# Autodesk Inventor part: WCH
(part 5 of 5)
hole "Díra1793" diameter "d16136" = 9.84314; stored, may be unused: countersink angle "d16140" = 90 deg, drill point angle "d16142" = 0 deg; dims "d16134" = 197, "d16135" = 318, "d16137" = 6, "d16138" = 4, "d16139" = 2, "d16141" = 8
hole "Díra1794" diameter "d16145" = 9.84314; stored, may be unused: countersink angle "d16149" = 90 deg, drill point angle "d16151" = 0 deg; dims "d16143" = 208, "d16144" = 318, "d16146" = 6, "d16147" = 4, "d16148" = 2, "d16150" = 8
hole "Díra1795" diameter "d16154" = 9.84314; stored, may be unused: countersink angle "d16158" = 90 deg, drill point angle "d16160" = 0 deg; dims "d16152" = 219, "d16153" = 318, "d16155" = 6, "d16156" = 4, "d16157" = 2, "d16159" = 8
hole "Díra1796" diameter "d16163" = 9.84314; stored, may be unused: countersink angle "d16167" = 90 deg, drill point angle "d16169" = 0 deg; dims "d16161" = 230, "d16162" = 318, "d16164" = 6, "d16165" = 4, "d16166" = 2, "d16168" = 8
hole "Díra1797" diameter "d16172" = 9.84314; stored, may be unused: countersink angle "d16176" = 90 deg, drill point angle "d16178" = 0 deg; dims "d16170" = 241, "d16171" = 318, "d16173" = 6, "d16174" = 4, "d16175" = 2, "d16177" = 8
hole "Díra1798" diameter "d16181" = 9.92157; stored, may be unused: countersink angle "d16185" = 90 deg, drill point angle "d16187" = 0 deg; dims "d16179" = 252, "d16180" = 318, "d16182" = 6, "d16183" = 4, "d16184" = 2, "d16186" = 8
hole "Díra1799" diameter "d16190" = 9.80392; stored, may be unused: countersink angle "d16194" = 90 deg, drill point angle "d16196" = 0 deg; dims "d16188" = 263, "d16189" = 318, "d16191" = 6, "d16192" = 4, "d16193" = 2, "d16195" = 8
hole "Díra1800" diameter "d16199" = 9.17647; stored, may be unused: countersink angle "d16203" = 90 deg, drill point angle "d16205" = 0 deg; dims "d16197" = 274, "d16198" = 318, "d16200" = 6, "d16201" = 4, "d16202" = 2, "d16204" = 8
hole "Díra1801" diameter "d16208" = 10; stored, may be unused: countersink angle "d16212" = 90 deg, drill point angle "d16214" = 0 deg; dims "d16206" = 285, "d16207" = 318, "d16209" = 6, "d16210" = 4, "d16211" = 2, "d16213" = 8
hole "Díra1802" diameter "d16217" = 10; stored, may be unused: countersink angle "d16221" = 90 deg, drill point angle "d16223" = 0 deg; dims "d16215" = 296, "d16216" = 318, "d16218" = 6, "d16219" = 4, "d16220" = 2, "d16222" = 8
hole "Díra1803" diameter "d16226" = 10; stored, may be unused: countersink angle "d16230" = 90 deg, drill point angle "d16232" = 0 deg; dims "d16224" = 307, "d16225" = 318, "d16227" = 6, "d16228" = 4, "d16229" = 2, "d16231" = 8
hole "Díra1804" diameter "d16235" = 10; stored, may be unused: countersink angle "d16239" = 90 deg, drill point angle "d16241" = 0 deg; dims "d16233" = 318, "d16234" = 318, "d16236" = 6, "d16237" = 4, "d16238" = 2, "d16240" = 8
hole "Díra1805" diameter "d16244" = 10; stored, may be unused: countersink angle "d16248" = 90 deg, drill point angle "d16250" = 0 deg; dims "d16242" = 329, "d16243" = 318, "d16245" = 6, "d16246" = 4, "d16247" = 2, "d16249" = 8
hole "Díra1806" diameter "d16253" = 10; stored, may be unused: countersink angle "d16257" = 90 deg, drill point angle "d16259" = 0 deg; dims "d16251" = 340, "d16252" = 318, "d16254" = 6, "d16255" = 4, "d16256" = 2, "d16258" = 8
hole "Díra1807" diameter "d16262" = 3.84314; stored, may be unused: countersink angle "d16266" = 90 deg, drill point angle "d16268" = 0 deg; dims "d16260" = 351, "d16261" = 318, "d16263" = 6, "d16264" = 4, "d16265" = 2, "d16267" = 8
hole "Díra1808" diameter "d16271" = 3.4902; stored, may be unused: countersink angle "d16275" = 90 deg, drill point angle "d16277" = 0 deg; dims "d16269" = 10, "d16270" = 329, "d16272" = 6, "d16273" = 4, "d16274" = 2, "d16276" = 8
hole "Díra1809" diameter "d16280" = 3.33333; stored, may be unused: countersink angle "d16284" = 90 deg, drill point angle "d16286" = 0 deg; dims "d16278" = 21, "d16279" = 329, "d16281" = 6, "d16282" = 4, "d16283" = 2, "d16285" = 8
hole "Díra1810" diameter "d16289" = 3.83007; stored, may be unused: countersink angle "d16293" = 90 deg, drill point angle "d16295" = 0 deg; dims "d16287" = 32, "d16288" = 329, "d16290" = 6, "d16291" = 4, "d16292" = 2, "d16294" = 8
hole "Díra1811" diameter "d16298" = 3.4902; stored, may be unused: countersink angle "d16302" = 90 deg, drill point angle "d16304" = 0 deg; dims "d16296" = 43, "d16297" = 329, "d16299" = 6, "d16300" = 4, "d16301" = 2, "d16303" = 8
hole "Díra1812" diameter "d16307" = 2.66667; stored, may be unused: countersink angle "d16311" = 90 deg, drill point angle "d16313" = 0 deg; dims "d16305" = 54, "d16306" = 329, "d16308" = 6, "d16309" = 4, "d16310" = 2, "d16312" = 8
hole "Díra1813" diameter "d16316" = 2.66667; stored, may be unused: countersink angle "d16320" = 90 deg, drill point angle "d16322" = 0 deg; dims "d16314" = 65, "d16315" = 329, "d16317" = 6, "d16318" = 4, "d16319" = 2, "d16321" = 8
hole "Díra1814" diameter "d16325" = 2.7451; stored, may be unused: countersink angle "d16329" = 90 deg, drill point angle "d16331" = 0 deg; dims "d16323" = 76, "d16324" = 329, "d16326" = 6, "d16327" = 4, "d16328" = 2, "d16330" = 8
hole "Díra1815" diameter "d16334" = 8.90196; stored, may be unused: countersink angle "d16338" = 90 deg, drill point angle "d16340" = 0 deg; dims "d16332" = 87, "d16333" = 329, "d16335" = 6, "d16336" = 4, "d16337" = 2, "d16339" = 8
hole "Díra1816" diameter "d16343" = 10; stored, may be unused: countersink angle "d16347" = 90 deg, drill point angle "d16349" = 0 deg; dims "d16341" = 98, "d16342" = 329, "d16344" = 6, "d16345" = 4, "d16346" = 2, "d16348" = 8
hole "Díra1817" diameter "d16352" = 10; stored, may be unused: countersink angle "d16356" = 90 deg, drill point angle "d16358" = 0 deg; dims "d16350" = 109, "d16351" = 329, "d16353" = 6, "d16354" = 4, "d16355" = 2, "d16357" = 8
hole "Díra1818" diameter "d16361" = 10; stored, may be unused: countersink angle "d16365" = 90 deg, drill point angle "d16367" = 0 deg; dims "d16359" = 120, "d16360" = 329, "d16362" = 6, "d16363" = 4, "d16364" = 2, "d16366" = 8
hole "Díra1819" diameter "d16370" = 10; stored, may be unused: countersink angle "d16374" = 90 deg, drill point angle "d16376" = 0 deg; dims "d16368" = 131, "d16369" = 329, "d16371" = 6, "d16372" = 4, "d16373" = 2, "d16375" = 8
hole "Díra1820" diameter "d16379" = 10; stored, may be unused: countersink angle "d16383" = 90 deg, drill point angle "d16385" = 0 deg; dims "d12975" = 109, "d12976" = 186, "d16377" = 142, "d16378" = 329, "d16380" = 6, "d16381" = 4, "d16382" = 2, "d16384" = 8
hole "Díra1821" diameter "d16388" = 9.68628; stored, may be unused: countersink angle "d16392" = 90 deg, drill point angle "d16394" = 0 deg; dims "d16386" = 153, "d16387" = 329, "d16389" = 6, "d16390" = 4, "d16391" = 2, "d16393" = 8
hole "Díra1822" diameter "d16397" = 9.45098; stored, may be unused: countersink angle "d16401" = 90 deg, drill point angle "d16403" = 0 deg; dims "d16395" = 164, "d16396" = 329, "d16398" = 6, "d16399" = 4, "d16400" = 2, "d16402" = 8
hole "Díra1823" diameter "d16406" = 9.41177; stored, may be unused: countersink angle "d16410" = 90 deg, drill point angle "d16412" = 0 deg; dims "d16404" = 175, "d16405" = 329, "d16407" = 6, "d16408" = 4, "d16409" = 2, "d16411" = 8
hole "Díra1824" diameter "d16415" = 8.98039; stored, may be unused: countersink angle "d16419" = 90 deg, drill point angle "d16421" = 0 deg; dims "d16413" = 186, "d16414" = 329, "d16416" = 6, "d16417" = 4, "d16418" = 2, "d16420" = 8
hole "Díra1825" diameter "d16424" = 8.90196; stored, may be unused: countersink angle "d16428" = 90 deg, drill point angle "d16430" = 0 deg; dims "d16422" = 197, "d16423" = 329, "d16425" = 6, "d16426" = 4, "d16427" = 2, "d16429" = 8
hole "Díra1826" diameter "d16433" = 8.78431; stored, may be unused: countersink angle "d16437" = 90 deg, drill point angle "d16439" = 0 deg; dims "d16431" = 208, "d16432" = 329, "d16434" = 6, "d16435" = 4, "d16436" = 2, "d16438" = 8
hole "Díra1827" diameter "d16442" = 8.43137; stored, may be unused: countersink angle "d16446" = 90 deg, drill point angle "d16448" = 0 deg; dims "d16440" = 219, "d16441" = 329, "d16443" = 6, "d16444" = 4, "d16445" = 2, "d16447" = 8
hole "Díra1828" diameter "d16451" = 8.39216; stored, may be unused: countersink angle "d16455" = 90 deg, drill point angle "d16457" = 0 deg; dims "d16449" = 230, "d16450" = 329, "d16452" = 6, "d16453" = 4, "d16454" = 2, "d16456" = 8
hole "Díra1829" diameter "d16460" = 7.96078; stored, may be unused: countersink angle "d16464" = 90 deg, drill point angle "d16466" = 0 deg; dims "d16458" = 241, "d16459" = 329, "d16461" = 6, "d16462" = 4, "d16463" = 2, "d16465" = 8
hole "Díra1830" diameter "d16469" = 7.80392; stored, may be unused: countersink angle "d16473" = 90 deg, drill point angle "d16475" = 0 deg; dims "d16467" = 252, "d16468" = 329, "d16470" = 6, "d16471" = 4, "d16472" = 2, "d16474" = 8
hole "Díra1831" diameter "d16478" = 7.29412; stored, may be unused: countersink angle "d16482" = 90 deg, drill point angle "d16484" = 0 deg; dims "d16476" = 263, "d16477" = 329, "d16479" = 6, "d16480" = 4, "d16481" = 2, "d16483" = 8
hole "Díra1832" diameter "d16487" = 7.68628; stored, may be unused: countersink angle "d16491" = 90 deg, drill point angle "d16493" = 0 deg; dims "d16485" = 274, "d16486" = 329, "d16488" = 6, "d16489" = 4, "d16490" = 2, "d16492" = 8
hole "Díra1833" diameter "d16496" = 4.62745; stored, may be unused: countersink angle "d16500" = 90 deg, drill point angle "d16502" = 0 deg; dims "d16494" = 285, "d16495" = 329, "d16497" = 6, "d16498" = 4, "d16499" = 2, "d16501" = 8
hole "Díra1834" diameter "d16505" = 2.66667; stored, may be unused: countersink angle "d16509" = 90 deg, drill point angle "d16511" = 0 deg; dims "d16503" = 296, "d16504" = 329, "d16506" = 6, "d16507" = 4, "d16508" = 2, "d16510" = 8
hole "Díra1835" diameter "d16514" = 4.82353; stored, may be unused: countersink angle "d16518" = 90 deg, drill point angle "d16520" = 0 deg; dims "d16512" = 307, "d16513" = 329, "d16515" = 6, "d16516" = 4, "d16517" = 2, "d16519" = 8
hole "Díra1836" diameter "d16523" = 5.64706; stored, may be unused: countersink angle "d16527" = 90 deg, drill point angle "d16529" = 0 deg; dims "d16521" = 318, "d16522" = 329, "d16524" = 6, "d16525" = 4, "d16526" = 2, "d16528" = 8
hole "Díra1837" diameter "d16532" = 4.78431; stored, may be unused: countersink angle "d16536" = 90 deg, drill point angle "d16538" = 0 deg; dims "d16530" = 329, "d16531" = 329, "d16533" = 6, "d16534" = 4, "d16535" = 2, "d16537" = 8
hole "Díra1838" diameter "d16541" = 2.56209; stored, may be unused: countersink angle "d16545" = 90 deg, drill point angle "d16547" = 0 deg; dims "d16539" = 340, "d16540" = 329, "d16542" = 6, "d16543" = 4, "d16544" = 2, "d16546" = 8
hole "Díra1839" diameter "d16550" = 0.78431; stored, may be unused: countersink angle "d16554" = 90 deg, drill point angle "d16556" = 0 deg; dims "d16548" = 351, "d16549" = 329, "d16551" = 6, "d16552" = 4, "d16553" = 2, "d16555" = 8
hole "Díra1840" diameter "d16559" = 4.19608; stored, may be unused: countersink angle "d16563" = 90 deg, drill point angle "d16565" = 0 deg; dims "d16557" = 10, "d16558" = 340, "d16560" = 6, "d16561" = 4, "d16562" = 2, "d16564" = 8
hole "Díra1841" diameter "d16568" = 4.90196; stored, may be unused: countersink angle "d16572" = 90 deg, drill point angle "d16574" = 0 deg; dims "d16566" = 21, "d16567" = 340, "d16569" = 6, "d16570" = 4, "d16571" = 2, "d16573" = 8
hole "Díra1842" diameter "d16577" = 5.41177; stored, may be unused: countersink angle "d16581" = 90 deg, drill point angle "d16583" = 0 deg; dims "d16575" = 32, "d16576" = 340, "d16578" = 6, "d16579" = 4, "d16580" = 2, "d16582" = 8
hole "Díra1843" diameter "d16586" = 3.84314; stored, may be unused: countersink angle "d16590" = 90 deg, drill point angle "d16592" = 0 deg; dims "d16584" = 43, "d16585" = 340, "d16587" = 6, "d16588" = 4, "d16589" = 2, "d16591" = 8
hole "Díra1844" diameter "d16595" = 2.19608; stored, may be unused: countersink angle "d16599" = 90 deg, drill point angle "d16601" = 0 deg; dims "d16593" = 54, "d16594" = 340, "d16596" = 6, "d16597" = 4, "d16598" = 2, "d16600" = 8
hole "Díra1845" diameter "d16604" = 1.52941; stored, may be unused: countersink angle "d16608" = 90 deg, drill point angle "d16610" = 0 deg; dims "d16602" = 65, "d16603" = 340, "d16605" = 6, "d16606" = 4, "d16607" = 2, "d16609" = 8
hole "Díra1846" diameter "d16613" = 1.29412; stored, may be unused: countersink angle "d16617" = 90 deg, drill point angle "d16619" = 0 deg; dims "d16611" = 76, "d16612" = 340, "d16614" = 6, "d16615" = 4, "d16616" = 2, "d16618" = 8
hole "Díra1847" diameter "d16622" = 8.54902; stored, may be unused: countersink angle "d16626" = 90 deg, drill point angle "d16628" = 0 deg; dims "d16620" = 87, "d16621" = 340, "d16623" = 6, "d16624" = 4, "d16625" = 2, "d16627" = 8
hole "Díra1848" diameter "d16631" = 10; stored, may be unused: countersink angle "d16635" = 90 deg, drill point angle "d16637" = 0 deg; dims "d16629" = 98, "d16630" = 340, "d16632" = 6, "d16633" = 4, "d16634" = 2, "d16636" = 8
hole "Díra1849" diameter "d16640" = 10; stored, may be unused: countersink angle "d16644" = 90 deg, drill point angle "d16646" = 0 deg; dims "d16638" = 109, "d16639" = 340, "d16641" = 6, "d16642" = 4, "d16643" = 2, "d16645" = 8
hole "Díra1850" diameter "d16649" = 10; stored, may be unused: countersink angle "d16653" = 90 deg, drill point angle "d16655" = 0 deg; dims "d16647" = 120, "d16648" = 340, "d16650" = 6, "d16651" = 4, "d16652" = 2, "d16654" = 8
hole "Díra1851" diameter "d16658" = 10; stored, may be unused: countersink angle "d16662" = 90 deg, drill point angle "d16664" = 0 deg; dims "d16656" = 131, "d16657" = 340, "d16659" = 6, "d16660" = 4, "d16661" = 2, "d16663" = 8
hole "Díra1852" diameter "d16667" = 10; stored, may be unused: countersink angle "d16671" = 90 deg, drill point angle "d16673" = 0 deg; dims "d16665" = 142, "d16666" = 340, "d16668" = 6, "d16669" = 4, "d16670" = 2, "d16672" = 8
hole "Díra1853" diameter "d16676" = 10; stored, may be unused: countersink angle "d16680" = 90 deg, drill point angle "d16682" = 0 deg; dims "d16674" = 153, "d16675" = 340, "d16677" = 6, "d16678" = 4, "d16679" = 2, "d16681" = 8
hole "Díra1854" diameter "d16685" = 10; stored, may be unused: countersink angle "d16689" = 90 deg, drill point angle "d16691" = 0 deg; dims "d16683" = 164, "d16684" = 340, "d16686" = 6, "d16687" = 4, "d16688" = 2, "d16690" = 8
hole "Díra1855" diameter "d16694" = 10; stored, may be unused: countersink angle "d16698" = 90 deg, drill point angle "d16700" = 0 deg; dims "d16692" = 175, "d16693" = 340, "d16695" = 6, "d16696" = 4, "d16697" = 2, "d16699" = 8
hole "Díra1856" diameter "d16703" = 10; stored, may be unused: countersink angle "d16707" = 90 deg, drill point angle "d16709" = 0 deg; dims "d16701" = 186, "d16702" = 340, "d16704" = 6, "d16705" = 4, "d16706" = 2, "d16708" = 8
hole "Díra1857" diameter "d16712" = 10; stored, may be unused: countersink angle "d16716" = 90 deg, drill point angle "d16718" = 0 deg; dims "d16710" = 197, "d16711" = 340, "d16713" = 6, "d16714" = 4, "d16715" = 2, "d16717" = 8
hole "Díra1858" diameter "d16721" = 10; stored, may be unused: countersink angle "d16725" = 90 deg, drill point angle "d16727" = 0 deg; dims "d16719" = 208, "d16720" = 340, "d16722" = 6, "d16723" = 4, "d16724" = 2, "d16726" = 8
hole "Díra1859" diameter "d16730" = 10; stored, may be unused: countersink angle "d16734" = 90 deg, drill point angle "d16736" = 0 deg; dims "d16728" = 219, "d16729" = 340, "d16731" = 6, "d16732" = 4, "d16733" = 2, "d16735" = 8
hole "Díra1860" diameter "d16739" = 10; stored, may be unused: countersink angle "d16743" = 90 deg, drill point angle "d16745" = 0 deg; dims "d16737" = 230, "d16738" = 340, "d16740" = 6, "d16741" = 4, "d16742" = 2, "d16744" = 8
hole "Díra1861" diameter "d16748" = 10; stored, may be unused: countersink angle "d16752" = 90 deg, drill point angle "d16754" = 0 deg; dims "d16746" = 241, "d16747" = 340, "d16749" = 6, "d16750" = 4, "d16751" = 2, "d16753" = 8
hole "Díra1862" diameter "d16757" = 9.29412; stored, may be unused: countersink angle "d16761" = 90 deg, drill point angle "d16763" = 0 deg; dims "d16755" = 252, "d16756" = 340, "d16758" = 6, "d16759" = 4, "d16760" = 2, "d16762" = 8
hole "Díra1863" diameter "d16766" = 7.29412; stored, may be unused: countersink angle "d16770" = 90 deg, drill point angle "d16772" = 0 deg; dims "d16764" = 263, "d16765" = 340, "d16767" = 6, "d16768" = 4, "d16769" = 2, "d16771" = 8
hole "Díra1864" diameter "d16775" = 7.68628; stored, may be unused: countersink angle "d16779" = 90 deg, drill point angle "d16781" = 0 deg; dims "d16773" = 274, "d16774" = 340, "d16776" = 6, "d16777" = 4, "d16778" = 2, "d16780" = 8
hole "Díra1865" diameter "d16784" = 1.29412; stored, may be unused: countersink angle "d16788" = 90 deg, drill point angle "d16790" = 0 deg; dims "d16782" = 285, "d16783" = 340, "d16785" = 6, "d16786" = 4, "d16787" = 2, "d16789" = 8
hole "Díra1866" diameter "d16793" = 4.19608; stored, may be unused: countersink angle "d16797" = 90 deg, drill point angle "d16799" = 0 deg; dims "d16791" = 10, "d16792" = 351, "d16794" = 6, "d16795" = 4, "d16796" = 2, "d16798" = 8
hole "Díra1867" diameter "d16802" = 4.86275; stored, may be unused: countersink angle "d16806" = 90 deg, drill point angle "d16808" = 0 deg; dims "d16800" = 21, "d16801" = 351, "d16803" = 6, "d16804" = 4, "d16805" = 2, "d16807" = 8
hole "Díra1868" diameter "d16811" = 5.2549; stored, may be unused: countersink angle "d16815" = 90 deg, drill point angle "d16817" = 0 deg; dims "d16809" = 32, "d16810" = 351, "d16812" = 6, "d16813" = 4, "d16814" = 2, "d16816" = 8
hole "Díra1869" diameter "d16820" = 3.80392; stored, may be unused: countersink angle "d16824" = 90 deg, drill point angle "d16826" = 0 deg; dims "d16818" = 43, "d16819" = 351, "d16821" = 6, "d16822" = 4, "d16823" = 2, "d16825" = 8
hole "Díra1870" diameter "d16829" = 2.47059; stored, may be unused: countersink angle "d16833" = 90 deg, drill point angle "d16835" = 0 deg; dims "d16827" = 54, "d16828" = 351, "d16830" = 6, "d16831" = 4, "d16832" = 2, "d16834" = 8
hole "Díra1871" diameter "d16838" = 1.96078; stored, may be unused: countersink angle "d16842" = 90 deg, drill point angle "d16844" = 0 deg; dims "d16836" = 65, "d16837" = 351, "d16839" = 6, "d16840" = 4, "d16841" = 2, "d16843" = 8
hole "Díra1872" diameter "d16847" = 1.13725; stored, may be unused: countersink angle "d16851" = 90 deg, drill point angle "d16853" = 0 deg; dims "d16845" = 76, "d16846" = 351, "d16848" = 6, "d16849" = 4, "d16850" = 2, "d16852" = 8
hole "Díra1873" diameter "d16856" = 7.4902; stored, may be unused: countersink angle "d16860" = 90 deg, drill point angle "d16862" = 0 deg; dims "d16854" = 87, "d16855" = 351, "d16857" = 6, "d16858" = 4, "d16859" = 2, "d16861" = 8
hole "Díra1874" diameter "d16865" = 10; stored, may be unused: countersink angle "d16869" = 90 deg, drill point angle "d16871" = 0 deg; dims "d16863" = 98, "d16864" = 351, "d16866" = 6, "d16867" = 4, "d16868" = 2, "d16870" = 8
hole "Díra1875" diameter "d16874" = 10; stored, may be unused: countersink angle "d16878" = 90 deg, drill point angle "d16880" = 0 deg; dims "d16872" = 109, "d16873" = 351, "d16875" = 6, "d16876" = 4, "d16877" = 2, "d16879" = 8
hole "Díra1876" diameter "d16883" = 10; stored, may be unused: countersink angle "d16887" = 90 deg, drill point angle "d16889" = 0 deg; dims "d16881" = 120, "d16882" = 351, "d16884" = 6, "d16885" = 4, "d16886" = 2, "d16888" = 8
hole "Díra1877" diameter "d16892" = 10; stored, may be unused: countersink angle "d16896" = 90 deg, drill point angle "d16898" = 0 deg; dims "d16890" = 131, "d16891" = 351, "d16893" = 6, "d16894" = 4, "d16895" = 2, "d16897" = 8
hole "Díra1878" diameter "d16901" = 10; stored, may be unused: countersink angle "d16905" = 90 deg, drill point angle "d16907" = 0 deg; dims "d16899" = 142, "d16900" = 351, "d16902" = 6, "d16903" = 4, "d16904" = 2, "d16906" = 8
hole "Díra1879" diameter "d16910" = 10; stored, may be unused: countersink angle "d16914" = 90 deg, drill point angle "d16916" = 0 deg; dims "d16908" = 153, "d16909" = 351, "d16911" = 6, "d16912" = 4, "d16913" = 2, "d16915" = 8
hole "Díra1880" diameter "d16919" = 10; stored, may be unused: countersink angle "d16923" = 90 deg, drill point angle "d16925" = 0 deg; dims "d16917" = 164, "d16918" = 351, "d16920" = 6, "d16921" = 4, "d16922" = 2, "d16924" = 8
hole "Díra1881" diameter "d16928" = 10; stored, may be unused: countersink angle "d16932" = 90 deg, drill point angle "d16934" = 0 deg; dims "d16926" = 175, "d16927" = 351, "d16929" = 6, "d16930" = 4, "d16931" = 2, "d16933" = 8
hole "Díra1882" diameter "d16937" = 10; stored, may be unused: countersink angle "d16941" = 90 deg, drill point angle "d16943" = 0 deg; dims "d16935" = 186, "d16936" = 351, "d16938" = 6, "d16939" = 4, "d16940" = 2, "d16942" = 8
hole "Díra1883" diameter "d16946" = 10; stored, may be unused: countersink angle "d16950" = 90 deg, drill point angle "d16952" = 0 deg; dims "d16944" = 197, "d16945" = 351, "d16947" = 6, "d16948" = 4, "d16949" = 2, "d16951" = 8
hole "Díra1884" diameter "d16955" = 10; stored, may be unused: countersink angle "d16959" = 90 deg, drill point angle "d16961" = 0 deg; dims "d16953" = 208, "d16954" = 351, "d16956" = 6, "d16957" = 4, "d16958" = 2, "d16960" = 8
hole "Díra1885" diameter "d16964" = 10; stored, may be unused: countersink angle "d16968" = 90 deg, drill point angle "d16970" = 0 deg; dims "d16962" = 219, "d16963" = 351, "d16965" = 6, "d16966" = 4, "d16967" = 2, "d16969" = 8
hole "Díra1886" diameter "d16973" = 10; stored, may be unused: countersink angle "d16977" = 90 deg, drill point angle "d16979" = 0 deg; dims "d16971" = 230, "d16972" = 351, "d16974" = 6, "d16975" = 4, "d16976" = 2, "d16978" = 8
hole "Díra1887" diameter "d16982" = 9.80392; stored, may be unused: countersink angle "d16986" = 90 deg, drill point angle "d16988" = 0 deg; dims "d16980" = 241, "d16981" = 351, "d16983" = 6, "d16984" = 4, "d16985" = 2, "d16987" = 8
hole "Díra1888" diameter "d16991" = 9.29412; stored, may be unused: countersink angle "d16995" = 90 deg, drill point angle "d16997" = 0 deg; dims "d16989" = 252, "d16990" = 351, "d16992" = 6, "d16993" = 4, "d16994" = 2, "d16996" = 8
hole "Díra1889" diameter "d17000" = 7.37255; stored, may be unused: countersink angle "d17004" = 90 deg, drill point angle "d17006" = 0 deg; dims "d16998" = 263, "d16999" = 351, "d17001" = 6, "d17002" = 4, "d17003" = 2, "d17005" = 8
hole "Díra1890" diameter "d17009" = 7.21569; stored, may be unused: countersink angle "d17013" = 90 deg, drill point angle "d17015" = 0 deg; dims "d17007" = 274, "d17008" = 351, "d17010" = 6, "d17011" = 4, "d17012" = 2, "d17014" = 8
hole "Díra1891" diameter "d17018" = 0.07843; stored, may be unused: countersink angle "d17022" = 90 deg, drill point angle "d17024" = 0 deg; dims "d17016" = 351, "d17017" = 351, "d17019" = 6, "d17020" = 4, "d17021" = 2, "d17023" = 8
hole "Díra1892" diameter "d17027" = 4.27451; stored, may be unused: countersink angle "d17031" = 90 deg, drill point angle "d17033" = 0 deg; dims "d17025" = 10, "d17026" = 362, "d17028" = 6, "d17029" = 4, "d17030" = 2, "d17032" = 8
hole "Díra1893" diameter "d17036" = 4.27451; stored, may be unused: countersink angle "d17040" = 90 deg, drill point angle "d17042" = 0 deg; dims "d17034" = 21, "d17035" = 362, "d17037" = 6, "d17038" = 4, "d17039" = 2, "d17041" = 8
hole "Díra1894" diameter "d17045" = 4.39216; stored, may be unused: countersink angle "d17049" = 90 deg, drill point angle "d17051" = 0 deg; dims "d17043" = 32, "d17044" = 362, "d17046" = 6, "d17047" = 4, "d17048" = 2, "d17050" = 8
hole "Díra1895" diameter "d17054" = 3.37255; stored, may be unused: countersink angle "d17058" = 90 deg, drill point angle "d17060" = 0 deg; dims "d17052" = 43, "d17053" = 362, "d17055" = 6, "d17056" = 4, "d17057" = 2, "d17059" = 8
hole "Díra1896" diameter "d17063" = 2.58824; stored, may be unused: countersink angle "d17067" = 90 deg, drill point angle "d17069" = 0 deg; dims "d17061" = 54, "d17062" = 362, "d17064" = 6, "d17065" = 4, "d17066" = 2, "d17068" = 8
hole "Díra1897" diameter "d17072" = 1.92157; stored, may be unused: countersink angle "d17076" = 90 deg, drill point angle "d17078" = 0 deg; dims "d17070" = 65, "d17071" = 362, "d17073" = 6, "d17074" = 4, "d17075" = 2, "d17077" = 8
hole "Díra1898" diameter "d17081" = 0.82353; stored, may be unused: countersink angle "d17085" = 90 deg, drill point angle "d17087" = 0 deg; dims "d17079" = 76, "d17080" = 362, "d17082" = 6, "d17083" = 4, "d17084" = 2, "d17086" = 8
hole "Díra1899" diameter "d17090" = 6.5098; stored, may be unused: countersink angle "d17094" = 90 deg, drill point angle "d17096" = 0 deg; dims "d17088" = 87, "d17089" = 362, "d17091" = 6, "d17092" = 4, "d17093" = 2, "d17095" = 8
hole "Díra1900" diameter "d17099" = 10; stored, may be unused: countersink angle "d17103" = 90 deg, drill point angle "d17105" = 0 deg; dims "d17097" = 98, "d17098" = 362, "d17100" = 6, "d17101" = 4, "d17102" = 2, "d17104" = 8
hole "Díra1901" diameter "d17108" = 10; stored, may be unused: countersink angle "d17112" = 90 deg, drill point angle "d17114" = 0 deg; dims "d17106" = 109, "d17107" = 362, "d17109" = 6, "d17110" = 4, "d17111" = 2, "d17113" = 8
hole "Díra1902" diameter "d17117" = 10; stored, may be unused: countersink angle "d17121" = 90 deg, drill point angle "d17123" = 0 deg; dims "d17115" = 120, "d17116" = 362, "d17118" = 6, "d17119" = 4, "d17120" = 2, "d17122" = 8
hole "Díra1903" diameter "d17126" = 10; stored, may be unused: countersink angle "d17130" = 90 deg, drill point angle "d17132" = 0 deg; dims "d17124" = 131, "d17125" = 362, "d17127" = 6, "d17128" = 4, "d17129" = 2, "d17131" = 8
hole "Díra1904" diameter "d17135" = 10; stored, may be unused: countersink angle "d17139" = 90 deg, drill point angle "d17141" = 0 deg; dims "d17133" = 142, "d17134" = 362, "d17136" = 6, "d17137" = 4, "d17138" = 2, "d17140" = 8
hole "Díra1905" diameter "d17144" = 10; stored, may be unused: countersink angle "d17148" = 90 deg, drill point angle "d17150" = 0 deg; dims "d17142" = 153, "d17143" = 362, "d17145" = 6, "d17146" = 4, "d17147" = 2, "d17149" = 8
hole "Díra1906" diameter "d17153" = 10; stored, may be unused: countersink angle "d17157" = 90 deg, drill point angle "d17159" = 0 deg; dims "d17151" = 164, "d17152" = 362, "d17154" = 6, "d17155" = 4, "d17156" = 2, "d17158" = 8
hole "Díra1907" diameter "d17162" = 10; stored, may be unused: countersink angle "d17166" = 90 deg, drill point angle "d17168" = 0 deg; dims "d17160" = 175, "d17161" = 362, "d17163" = 6, "d17164" = 4, "d17165" = 2, "d17167" = 8
hole "Díra1908" diameter "d17171" = 10; stored, may be unused: countersink angle "d17175" = 90 deg, drill point angle "d17177" = 0 deg; dims "d17169" = 186, "d17170" = 362, "d17172" = 6, "d17173" = 4, "d17174" = 2, "d17176" = 8
hole "Díra1909" diameter "d17180" = 10; stored, may be unused: countersink angle "d17184" = 90 deg, drill point angle "d17186" = 0 deg; dims "d17178" = 197, "d17179" = 362, "d17181" = 6, "d17182" = 4, "d17183" = 2, "d17185" = 8
hole "Díra1910" diameter "d17189" = 10; stored, may be unused: countersink angle "d17193" = 90 deg, drill point angle "d17195" = 0 deg; dims "d17187" = 208, "d17188" = 362, "d17190" = 6, "d17191" = 4, "d17192" = 2, "d17194" = 8
hole "Díra1911" diameter "d17198" = 10; stored, may be unused: countersink angle "d17202" = 90 deg, drill point angle "d17204" = 0 deg; dims "d17196" = 219, "d17197" = 362, "d17199" = 6, "d17200" = 4, "d17201" = 2, "d17203" = 8
hole "Díra1912" diameter "d17207" = 10; stored, may be unused: countersink angle "d17211" = 90 deg, drill point angle "d17213" = 0 deg; dims "d17205" = 230, "d17206" = 362, "d17208" = 6, "d17209" = 4, "d17210" = 2, "d17212" = 8
hole "Díra1913" diameter "d17216" = 9.80392; stored, may be unused: countersink angle "d17220" = 90 deg, drill point angle "d17222" = 0 deg; dims "d17214" = 241, "d17215" = 362, "d17217" = 6, "d17218" = 4, "d17219" = 2, "d17221" = 8
hole "Díra1914" diameter "d17225" = 8.5098; stored, may be unused: countersink angle "d17229" = 90 deg, drill point angle "d17231" = 0 deg; dims "d17223" = 252, "d17224" = 362, "d17226" = 6, "d17227" = 4, "d17228" = 2, "d17230" = 8
hole "Díra1915" diameter "d17234" = 6.7451; stored, may be unused: countersink angle "d17238" = 90 deg, drill point angle "d17240" = 0 deg; dims "d17232" = 263, "d17233" = 362, "d17235" = 6, "d17236" = 4, "d17237" = 2, "d17239" = 8
hole "Díra1916" diameter "d17243" = 5.4902; stored, may be unused: countersink angle "d17247" = 90 deg, drill point angle "d17249" = 0 deg; dims "d17241" = 274, "d17242" = 362, "d17244" = 6, "d17245" = 4, "d17246" = 2, "d17248" = 8
hole "Díra1917" diameter "d17252" = 0.07843; stored, may be unused: countersink angle "d17256" = 90 deg, drill point angle "d17258" = 0 deg; dims "d17250" = 351, "d17251" = 362, "d17253" = 6, "d17254" = 4, "d17255" = 2, "d17257" = 8
hole "Díra1918" diameter "d17261" = 4.27451; stored, may be unused: countersink angle "d17265" = 90 deg, drill point angle "d17267" = 0 deg; dims "d17259" = 10, "d17260" = 373, "d17262" = 6, "d17263" = 4, "d17264" = 2, "d17266" = 8
hole "Díra1919" diameter "d17270" = 3.64706; stored, may be unused: countersink angle "d17274" = 90 deg, drill point angle "d17276" = 0 deg; dims "d17268" = 21, "d17269" = 373, "d17271" = 6, "d17272" = 4, "d17273" = 2, "d17275" = 8
hole "Díra1920" diameter "d17279" = 3.76471; stored, may be unused: countersink angle "d17283" = 90 deg, drill point angle "d17285" = 0 deg; dims "d17277" = 32, "d17278" = 373, "d17280" = 6, "d17281" = 4, "d17282" = 2, "d17284" = 8
hole "Díra1921" diameter "d17288" = 3.29412; stored, may be unused: countersink angle "d17292" = 90 deg, drill point angle "d17294" = 0 deg; dims "d17286" = 43, "d17287" = 373, "d17289" = 6, "d17290" = 4, "d17291" = 2, "d17293" = 8
hole "Díra1922" diameter "d17297" = 2.47059; stored, may be unused: countersink angle "d17301" = 90 deg, drill point angle "d17303" = 0 deg; dims "d17295" = 54, "d17296" = 373, "d17298" = 6, "d17299" = 4, "d17300" = 2, "d17302" = 8
hole "Díra1923" diameter "d17306" = 1.72549; stored, may be unused: countersink angle "d17310" = 90 deg, drill point angle "d17312" = 0 deg; dims "d17304" = 65, "d17305" = 373, "d17307" = 6, "d17308" = 4, "d17309" = 2, "d17311" = 8
hole "Díra1924" diameter "d17315" = 0.78431; stored, may be unused: countersink angle "d17319" = 90 deg, drill point angle "d17321" = 0 deg; dims "d17313" = 76, "d17314" = 373, "d17316" = 6, "d17317" = 4, "d17318" = 2, "d17320" = 8
hole "Díra1925" diameter "d17324" = 6.19608; stored, may be unused: countersink angle "d17328" = 90 deg, drill point angle "d17330" = 0 deg; dims "d17322" = 87, "d17323" = 373, "d17325" = 6, "d17326" = 4, "d17327" = 2, "d17329" = 8
hole "Díra1926" diameter "d17333" = 10; stored, may be unused: countersink angle "d17337" = 90 deg, drill point angle "d17339" = 0 deg; dims "d17331" = 98, "d17332" = 373, "d17334" = 6, "d17335" = 4, "d17336" = 2, "d17338" = 8
hole "Díra1927" diameter "d17342" = 10; stored, may be unused: countersink angle "d17346" = 90 deg, drill point angle "d17348" = 0 deg; dims "d17340" = 109, "d17341" = 373, "d17343" = 6, "d17344" = 4, "d17345" = 2, "d17347" = 8
hole "Díra1928" diameter "d17351" = 10; stored, may be unused: countersink angle "d17355" = 90 deg, drill point angle "d17357" = 0 deg; dims "d17349" = 120, "d17350" = 373, "d17352" = 6, "d17353" = 4, "d17354" = 2, "d17356" = 8
hole "Díra1929" diameter "d17360" = 10; stored, may be unused: countersink angle "d17364" = 90 deg, drill point angle "d17366" = 0 deg; dims "d17358" = 131, "d17359" = 373, "d17361" = 6, "d17362" = 4, "d17363" = 2, "d17365" = 8
hole "Díra1930" diameter "d17369" = 10; stored, may be unused: countersink angle "d17373" = 90 deg, drill point angle "d17375" = 0 deg; dims "d17367" = 142, "d17368" = 373, "d17370" = 6, "d17371" = 4, "d17372" = 2, "d17374" = 8
hole "Díra1931" diameter "d17378" = 10; stored, may be unused: countersink angle "d17382" = 90 deg, drill point angle "d17384" = 0 deg; dims "d17376" = 153, "d17377" = 373, "d17379" = 6, "d17380" = 4, "d17381" = 2, "d17383" = 8
hole "Díra1932" diameter "d17387" = 10; stored, may be unused: countersink angle "d17391" = 90 deg, drill point angle "d17393" = 0 deg; dims "d17385" = 164, "d17386" = 373, "d17388" = 6, "d17389" = 4, "d17390" = 2, "d17392" = 8
hole "Díra1933" diameter "d17396" = 10; stored, may be unused: countersink angle "d17400" = 90 deg, drill point angle "d17402" = 0 deg; dims "d17394" = 175, "d17395" = 373, "d17397" = 6, "d17398" = 4, "d17399" = 2, "d17401" = 8
hole "Díra1934" diameter "d17405" = 10; stored, may be unused: countersink angle "d17409" = 90 deg, drill point angle "d17411" = 0 deg; dims "d17403" = 186, "d17404" = 373, "d17406" = 6, "d17407" = 4, "d17408" = 2, "d17410" = 8
hole "Díra1935" diameter "d17414" = 10; stored, may be unused: countersink angle "d17418" = 90 deg, drill point angle "d17420" = 0 deg; dims "d17412" = 197, "d17413" = 373, "d17415" = 6, "d17416" = 4, "d17417" = 2, "d17419" = 8
hole "Díra1936" diameter "d17423" = 10; stored, may be unused: countersink angle "d17427" = 90 deg, drill point angle "d17429" = 0 deg; dims "d17421" = 208, "d17422" = 373, "d17424" = 6, "d17425" = 4, "d17426" = 2, "d17428" = 8
hole "Díra1937" diameter "d17432" = 10; stored, may be unused: countersink angle "d17436" = 90 deg, drill point angle "d17438" = 0 deg; dims "d17430" = 219, "d17431" = 373, "d17433" = 6, "d17434" = 4, "d17435" = 2, "d17437" = 8
hole "Díra1938" diameter "d17441" = 10; stored, may be unused: countersink angle "d17445" = 90 deg, drill point angle "d17447" = 0 deg; dims "d17439" = 230, "d17440" = 373, "d17442" = 6, "d17443" = 4, "d17444" = 2, "d17446" = 8
hole "Díra1939" diameter "d17450" = 9.52941; stored, may be unused: countersink angle "d17454" = 90 deg, drill point angle "d17456" = 0 deg; dims "d17448" = 241, "d17449" = 373, "d17451" = 6, "d17452" = 4, "d17453" = 2, "d17455" = 8
hole "Díra1940" diameter "d17459" = 8.43137; stored, may be unused: countersink angle "d17463" = 90 deg, drill point angle "d17465" = 0 deg; dims "d17457" = 252, "d17458" = 373, "d17460" = 6, "d17461" = 4, "d17462" = 2, "d17464" = 8
hole "Díra1941" diameter "d17468" = 7.37255; stored, may be unused: countersink angle "d17472" = 90 deg, drill point angle "d17474" = 0 deg; dims "d17466" = 263, "d17467" = 373, "d17469" = 6, "d17470" = 4, "d17471" = 2, "d17473" = 8
hole "Díra1942" diameter "d17477" = 3.13726; stored, may be unused: countersink angle "d17481" = 90 deg, drill point angle "d17483" = 0 deg; dims "d17475" = 274, "d17476" = 373, "d17478" = 6, "d17479" = 4, "d17480" = 2, "d17482" = 8
hole "Díra1943" diameter "d17486" = 0.05229; stored, may be unused: countersink angle "d17490" = 90 deg, drill point angle "d17492" = 0 deg; dims "d17484" = 351, "d17485" = 373, "d17487" = 6, "d17488" = 4, "d17489" = 2, "d17491" = 8
hole "Díra1944" diameter "d17495" = 3.29412; stored, may be unused: countersink angle "d17499" = 90 deg, drill point angle "d17501" = 0 deg; dims "d17493" = 10, "d17494" = 384, "d17496" = 6, "d17497" = 4, "d17498" = 2, "d17500" = 8
hole "Díra1945" diameter "d17504" = 2.90196; stored, may be unused: countersink angle "d17508" = 90 deg, drill point angle "d17510" = 0 deg; dims "d17502" = 21, "d17503" = 384, "d17505" = 6, "d17506" = 4, "d17507" = 2, "d17509" = 8
hole "Díra1946" diameter "d17513" = 3.76471; stored, may be unused: countersink angle "d17517" = 90 deg, drill point angle "d17519" = 0 deg; dims "d17511" = 32, "d17512" = 384, "d17514" = 6, "d17515" = 4, "d17516" = 2, "d17518" = 8
hole "Díra1947" diameter "d17522" = 3.09804; stored, may be unused: countersink angle "d17526" = 90 deg, drill point angle "d17528" = 0 deg; dims "d17520" = 43, "d17521" = 384, "d17523" = 6, "d17524" = 4, "d17525" = 2, "d17527" = 8
hole "Díra1948" diameter "d12977" = 4.27451; diameter "d17531" = 2.07843; stored, may be unused: countersink angle "d17535" = 90 deg, drill point angle "d17537" = 0 deg; dims "d17529" = 54, "d17530" = 384, "d17532" = 6, "d17533" = 4, "d17534" = 2, "d17536" = 8
hole "Díra1949" diameter "d17540" = 1.52941; stored, may be unused: countersink angle "d17544" = 90 deg, drill point angle "d17546" = 0 deg; dims "d17538" = 65, "d17539" = 384, "d17541" = 6, "d17542" = 4, "d17543" = 2, "d17545" = 8
hole "Díra1950" diameter "d17549" = 0.82353; stored, may be unused: countersink angle "d17553" = 90 deg, drill point angle "d17555" = 0 deg; dims "d17547" = 76, "d17548" = 384, "d17550" = 6, "d17551" = 4, "d17552" = 2, "d17554" = 8
hole "Díra1951" diameter "d17558" = 5.52941; stored, may be unused: countersink angle "d17562" = 90 deg, drill point angle "d17564" = 0 deg; dims "d17556" = 87, "d17557" = 384, "d17559" = 6, "d17560" = 4, "d17561" = 2, "d17563" = 8
hole "Díra1952" diameter "d17567" = 10; stored, may be unused: countersink angle "d17571" = 90 deg, drill point angle "d17573" = 0 deg; dims "d17565" = 98, "d17566" = 384, "d17568" = 6, "d17569" = 4, "d17570" = 2, "d17572" = 8
hole "Díra1953" diameter "d17576" = 10; stored, may be unused: countersink angle "d17580" = 90 deg, drill point angle "d17582" = 0 deg; dims "d17574" = 109, "d17575" = 384, "d17577" = 6, "d17578" = 4, "d17579" = 2, "d17581" = 8
hole "Díra1954" diameter "d17585" = 10; stored, may be unused: countersink angle "d17589" = 90 deg, drill point angle "d17591" = 0 deg; dims "d17583" = 120, "d17584" = 384, "d17586" = 6, "d17587" = 4, "d17588" = 2, "d17590" = 8
hole "Díra1955" diameter "d17594" = 10; stored, may be unused: countersink angle "d17598" = 90 deg, drill point angle "d17600" = 0 deg; dims "d17592" = 131, "d17593" = 384, "d17595" = 6, "d17596" = 4, "d17597" = 2, "d17599" = 8
hole "Díra1956" diameter "d17603" = 10; stored, may be unused: countersink angle "d17607" = 90 deg, drill point angle "d17609" = 0 deg; dims "d17601" = 142, "d17602" = 384, "d17604" = 6, "d17605" = 4, "d17606" = 2, "d17608" = 8
hole "Díra1957" diameter "d17612" = 10; stored, may be unused: countersink angle "d17616" = 90 deg, drill point angle "d17618" = 0 deg; dims "d17610" = 153, "d17611" = 384, "d17613" = 6, "d17614" = 4, "d17615" = 2, "d17617" = 8
hole "Díra1958" diameter "d17621" = 10; stored, may be unused: countersink angle "d17625" = 90 deg, drill point angle "d17627" = 0 deg; dims "d17619" = 164, "d17620" = 384, "d17622" = 6, "d17623" = 4, "d17624" = 2, "d17626" = 8
hole "Díra1959" diameter "d17630" = 10; stored, may be unused: countersink angle "d17634" = 90 deg, drill point angle "d17636" = 0 deg; dims "d17628" = 175, "d17629" = 384, "d17631" = 6, "d17632" = 4, "d17633" = 2, "d17635" = 8
hole "Díra1960" diameter "d17639" = 10; stored, may be unused: countersink angle "d17643" = 90 deg, drill point angle "d17645" = 0 deg; dims "d17637" = 186, "d17638" = 384, "d17640" = 6, "d17641" = 4, "d17642" = 2, "d17644" = 8
hole "Díra1961" diameter "d17648" = 10; stored, may be unused: countersink angle "d17652" = 90 deg, drill point angle "d17654" = 0 deg; dims "d17646" = 197, "d17647" = 384, "d17649" = 6, "d17650" = 4, "d17651" = 2, "d17653" = 8
hole "Díra1962" diameter "d17657" = 10; stored, may be unused: countersink angle "d17661" = 90 deg, drill point angle "d17663" = 0 deg; dims "d17655" = 208, "d17656" = 384, "d17658" = 6, "d17659" = 4, "d17660" = 2, "d17662" = 8
hole "Díra1963" diameter "d17666" = 10; stored, may be unused: countersink angle "d17670" = 90 deg, drill point angle "d17672" = 0 deg; dims "d17664" = 219, "d17665" = 384, "d17667" = 6, "d17668" = 4, "d17669" = 2, "d17671" = 8
hole "Díra1964" diameter "d17675" = 10; stored, may be unused: countersink angle "d17679" = 90 deg, drill point angle "d17681" = 0 deg; dims "d17673" = 230, "d17674" = 384, "d17676" = 6, "d17677" = 4, "d17678" = 2, "d17680" = 8
hole "Díra1965" diameter "d17684" = 10; stored, may be unused: countersink angle "d17688" = 90 deg, drill point angle "d17690" = 0 deg; dims "d17682" = 241, "d17683" = 384, "d17685" = 6, "d17686" = 4, "d17687" = 2, "d17689" = 8
hole "Díra1966" diameter "d17693" = 9.84314; stored, may be unused: countersink angle "d17697" = 90 deg, drill point angle "d17699" = 0 deg; dims "d17691" = 252, "d17692" = 384, "d17694" = 6, "d17695" = 4, "d17696" = 2, "d17698" = 8
hole "Díra1967" diameter "d17702" = 8.90196; stored, may be unused: countersink angle "d17706" = 90 deg, drill point angle "d17708" = 0 deg; dims "d17700" = 263, "d17701" = 384, "d17703" = 6, "d17704" = 4, "d17705" = 2, "d17707" = 8
hole "Díra1968" diameter "d17711" = 1.84314; stored, may be unused: countersink angle "d17715" = 90 deg, drill point angle "d17717" = 0 deg; dims "d17709" = 274, "d17710" = 384, "d17712" = 6, "d17713" = 4, "d17714" = 2, "d17716" = 8
hole "Díra1969" diameter "d17720" = 0.27451; stored, may be unused: countersink angle "d17724" = 90 deg, drill point angle "d17726" = 0 deg; dims "d17718" = 351, "d17719" = 384, "d17721" = 6, "d17722" = 4, "d17723" = 2, "d17725" = 8
node "Těleso3"
